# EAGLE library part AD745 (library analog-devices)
Ultralow Noise, High Speed, BiFET Op Amp Course: http://www.analog.com/static/imported-files/data_sheets/AD745.pdf
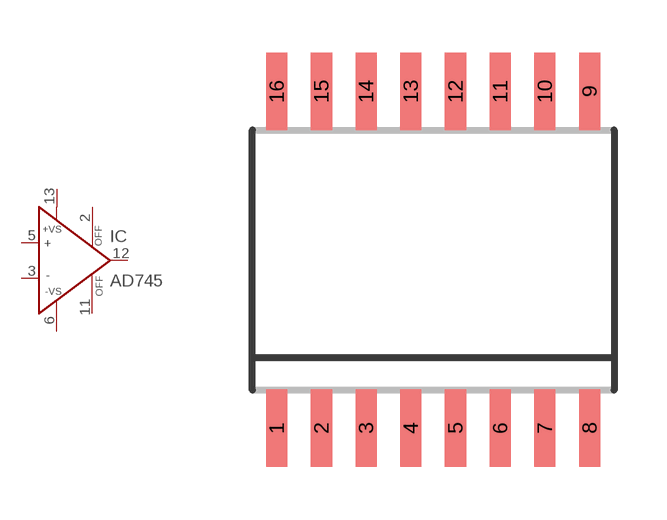
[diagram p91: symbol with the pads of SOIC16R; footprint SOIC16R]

Designator prefix IC

## AD745R (MF: ALTERA CORPORATION; MPN: AD745JRZ-16; OC_FARNELL: 1838876; OC_NEWARK: 59K4819)  [SOIC16R]
2  OFF  pas
3  IN-  in
5  IN+  in
6  -VS  in
11  OFF  pas
12  OUT  out
13  +VS  in

## Footprint SOIC16R (pad centres in mm)
16-Lead SOIC (R) Package Source: http://www.analog.com/static/imported-files/data_sheets/AD745.pdf
smd 0.6 x 2.2: 1 -4.445,-4.775; 2 -3.175,-4.775; 3 -1.905,-4.775; 4 -0.635,-4.775; 5 0.635,-4.775; 6 1.905,-4.775; 7 3.175,-4.775; 8 4.445,-4.775; 9 4.445,4.8; 10 3.175,4.8; 11 1.905,4.8; 12 0.635,4.8; 13 -0.635,4.8; 14 -1.905,4.8; 15 -3.175,4.8; 16 -4.445,4.8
